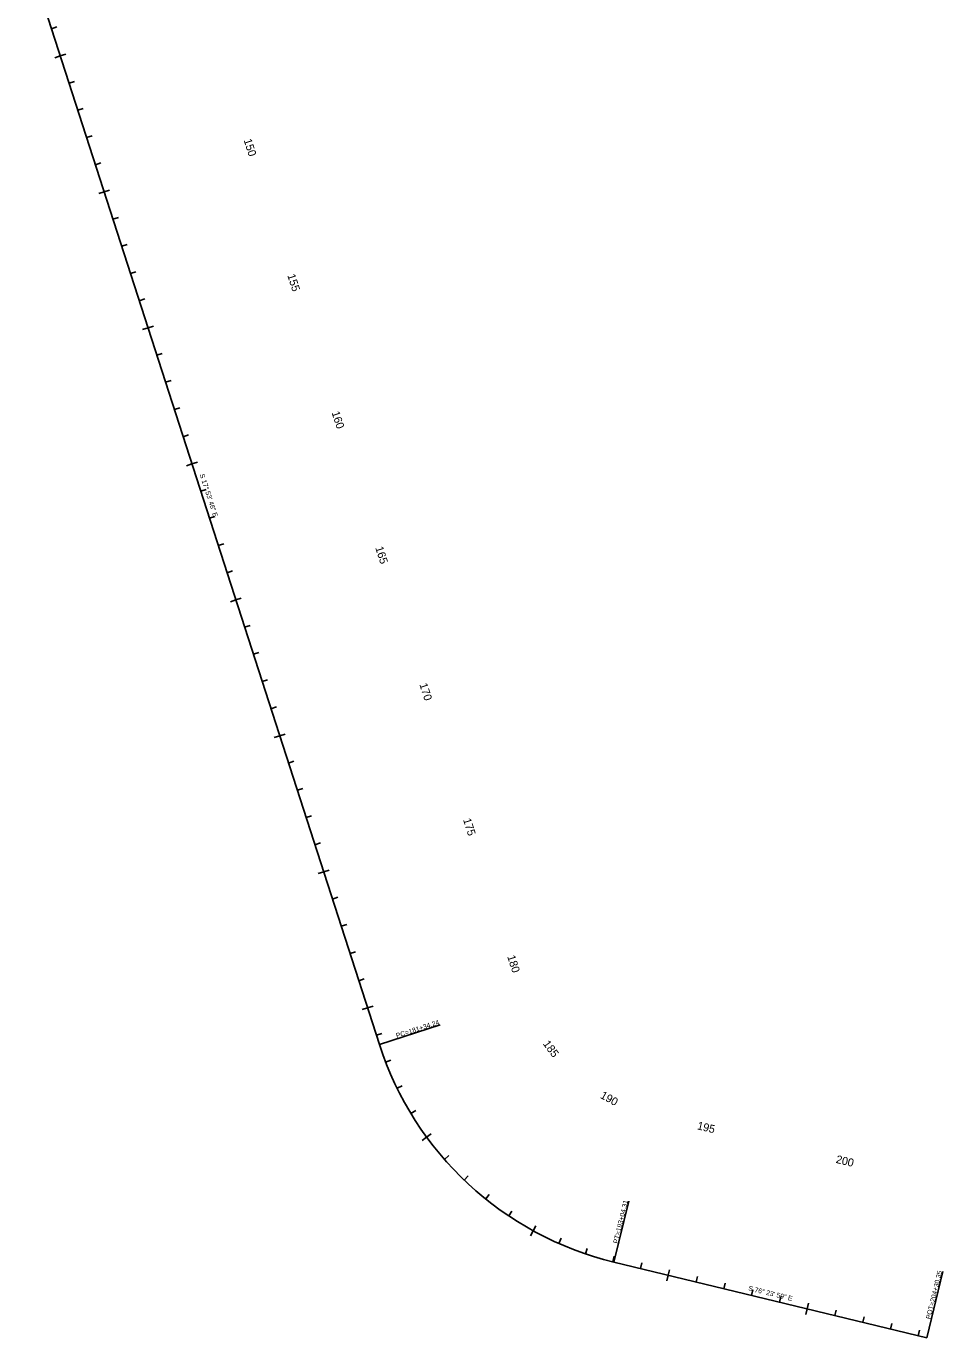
# Model space of a CAD drawing. Extents: x 2339300 to 2355400, y 360879 to 381052.
# Drawn here: x 2352193 to 2355400, y 360879 to 365467 of the extents above; entities that cross this region are included whole.
import ezdxf

# ---------------------------------------------------------------- set-up
doc = ezdxf.new("R2010")
doc.units = 0
for name, color, linetype in [('RD_HC_Cl', 7, 'Continuous'), ('RD_HC_Data', 7, 'Continuous'), ('RD_HC_Data_Tic', 7, 'Continuous'), ('RD_HC_TX_Sta50', 7, 'Continuous')]:
    doc.layers.add(name, color=color, linetype=linetype)

msp = doc.modelspace()

# ---------------------------------------------------------------- linework, layer by layer
at = {"layer": 'RD_HC_Cl'}
for p, q in [((2352192.8, 365732.2), (2353428.7, 361905)), ((2354249.7, 361143.4), (2355344.2, 360878.6))]:
    msp.add_line(p, q, dxfattribs=at)
msp.add_arc((2354519.1, 362257.1), 1145.9, 197.896, 256.3996, dxfattribs=at)
at = {"layer": 'RD_HC_Data'}
for p, q in [((2353428.7, 361905), (2353641.6, 361973.8)), ((2354249.7, 361143.4), (2354301.3, 361356.6)), ((2355344.2, 360878.6), (2355400.4, 361110.9))]:
    msp.add_line(p, q, dxfattribs=at)
at = {"layer": 'RD_HC_Data_Tic'}
for p, q in [((2352281.2, 365458.6), (2352300.2, 365464.7)), ((2352311.9, 365363.4), (2352292.9, 365357.3)), ((2352311.9, 365363.4), (2352330.9, 365369.6)), ((2352342.6, 365268.3), (2352361.7, 365274.4)), ((2352373.4, 365173.1), (2352392.4, 365179.2)), ((2352404.1, 365077.9), (2352423.1, 365084.1)), ((2352434.8, 364982.8), (2352453.9, 364988.9)), ((2352465.6, 364887.6), (2352446.5, 364881.5)), ((2352465.6, 364887.6), (2352484.6, 364893.8)), ((2352496.3, 364792.4), (2352515.3, 364798.6)), ((2352527, 364697.3), (2352546, 364703.4)), ((2352557.7, 364602.1), (2352576.8, 364608.3)), ((2352588.5, 364507), (2352607.5, 364513.1)), ((2352619.2, 364411.8), (2352600.2, 364405.7)), ((2352619.2, 364411.8), (2352638.2, 364417.9)), ((2352649.9, 364316.6), (2352669, 364322.8)), ((2352680.7, 364221.5), (2352699.7, 364227.6)), ((2352711.4, 364126.3), (2352730.4, 364132.5)), ((2352742.1, 364031.2), (2352761.1, 364037.3)), ((2352772.8, 363936), (2352753.8, 363929.8)), ((2352772.8, 363936), (2352791.9, 363942.1)), ((2352803.6, 363840.8), (2352822.6, 363847)), ((2352834.3, 363745.7), (2352853.3, 363751.8)), ((2352865, 363650.5), (2352884.1, 363656.7)), ((2352895.8, 363555.3), (2352914.8, 363561.5)), ((2352926.5, 363460.2), (2352907.5, 363454)), ((2352926.5, 363460.2), (2352945.5, 363466.3)), ((2352957.2, 363365), (2352976.2, 363371.2)), ((2352987.9, 363269.9), (2353007, 363276)), ((2353018.7, 363174.7), (2353037.7, 363180.8)), ((2353049.4, 363079.5), (2353068.4, 363085.7)), ((2353080.1, 362984.4), (2353061.1, 362978.2)), ((2353080.1, 362984.4), (2353099.2, 362990.5)), ((2353110.9, 362889.2), (2353129.9, 362895.4)), ((2353141.6, 362794.1), (2353160.6, 362800.2)), ((2353172.3, 362698.9), (2353191.4, 362705)), ((2353203, 362603.7), (2353222.1, 362609.9)), ((2353233.8, 362508.6), (2353252.8, 362514.7)), ((2353233.8, 362508.6), (2353214.7, 362502.4)), ((2353264.5, 362413.4), (2353283.5, 362419.6)), ((2353295.2, 362318.2), (2353314.3, 362324.4)), ((2353326, 362223.1), (2353345, 362229.2)), ((2353356.7, 362127.9), (2353375.7, 362134.1)), ((2353387.4, 362032.8), (2353368.4, 362026.6)), ((2353387.4, 362032.8), (2353406.5, 362038.9)), ((2353418.2, 361937.6), (2353437.2, 361943.7)), ((2353450.7, 361843.1), (2353469.3, 361850.3)), ((2353490.8, 361751.5), (2353508.8, 361760.3)), ((2353538.8, 361663.8), (2353555.9, 361674.2)), ((2353594.2, 361580.6), (2353610.4, 361592.4)), ((2353594.2, 361580.6), (2353578.1, 361568.8)), ((2353656.7, 361502.6), (2353671.8, 361515.8)), ((2353725.8, 361430.3), (2353739.6, 361444.7)), ((2353800.9, 361364.3), (2353813.4, 361379.9)), ((2353881.4, 361305.1), (2353892.5, 361321.7)), ((2353966.8, 361253.1), (2353976.5, 361270.7)), ((2353966.8, 361253.1), (2353957.2, 361235.6)), ((2354056.4, 361208.8), (2354064.5, 361227.1)), ((2354149.6, 361172.5), (2354156, 361191.4)), ((2354245.5, 361144.4), (2354250.3, 361163.8)), ((2354342.7, 361120.9), (2354347.4, 361140.3)), ((2354439.9, 361097.3), (2354435.2, 361077.9)), ((2354439.9, 361097.3), (2354444.6, 361116.8)), ((2354537.1, 361073.8), (2354541.8, 361093.3)), ((2354634.3, 361050.3), (2354639, 361069.8)), ((2354731.5, 361026.8), (2354736.2, 361046.2)), ((2354828.7, 361003.3), (2354833.4, 361022.7)), ((2354925.9, 360979.8), (2354930.6, 360999.2)), ((2354925.9, 360979.8), (2354921.2, 360960.3)), ((2355023.1, 360956.3), (2355027.8, 360975.7)), ((2355120.3, 360932.7), (2355125, 360952.2)), ((2355217.5, 360909.2), (2355222.2, 360928.7)), ((2355314.6, 360885.7), (2355319.4, 360905.2))]:
    msp.add_line(p, q, dxfattribs=at)

# ---------------------------------------------------------------- texts
at = {"layer": 'RD_HC_Data'}
for s, rotation, p in [('S 17%%d 53\' 46" E', 287.896, (2352799.6, 363898.6)), ('PC=181+34.24', 17.896, (2353489.9, 361926.9)), ('PT=193+04.31', 76.3996, (2354263, 361207)), ('POT=204+30.35', 76.3996, (2355357.5, 360942.2)), ('S 76%%d 23\' 59" E', 346.3996, (2354718.7, 361044.3))]:
    msp.add_text(s, height=17, rotation=rotation, dxfattribs=at).set_placement(p)
at = {"layer": 'RD_HC_TX_Sta50'}
for s, rotation, p in [('150', 287.896, (2352953.5, 365068.8)), ('155', 287.896, (2353106.2, 364595.9)), ('160', 287.896, (2353261.3, 364115.6)), ('165', 287.896, (2353414, 363642.7)), ('170', 287.896, (2353568.4, 363164.4)), ('175', 287.896, (2353721.1, 362691.5)), ('180', 287.896, (2353875.8, 362212.5)), ('185', 306.184, (2353999.8, 361907)), ('190', 331.1841, (2354199.2, 361718.8)), ('195', 346.3996, (2354538.9, 361608.4)), ('200', 346.3996, (2355024.5, 361490.9))]:
    msp.add_text(s, height=28, rotation=rotation, dxfattribs=at).set_placement(p)

doc.saveas('drawing.dxf')
